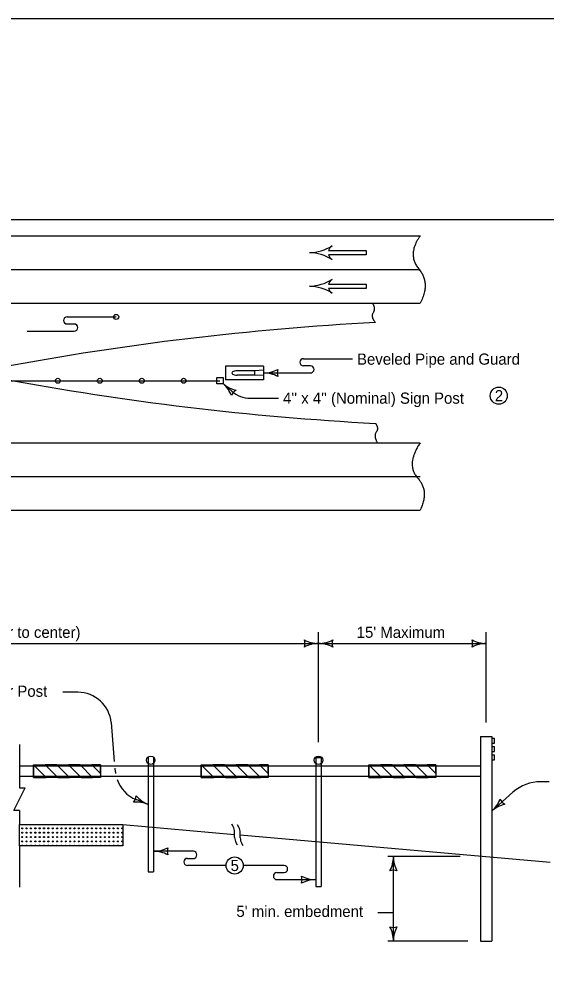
# Model space of a CAD drawing. Extents: x 228 to 3572, y -1307 to 1277.
# Drawn here: x 1702 to 2457, y -75 to 1277 of the extents above; entities that cross this region are included whole.
import ezdxf

# ---------------------------------------------------------------- set-up
doc = ezdxf.new("R2010")
doc.units = 0
for name, color, linetype in [('dsnShtPlotShapeBatchPrint', 7, 'Continuous'), ('dsnStdBorder', 7, 'Continuous'), ('dsnStdDimension', 7, 'Continuous'), ('Level 2', 7, 'Continuous'), ('Level 3', 7, 'Continuous')]:
    doc.layers.add(name, color=color, linetype=linetype)

msp = doc.modelspace()

# ---------------------------------------------------------------- linework, layer by layer
at = {"layer": 'dsnShtPlotShapeBatchPrint'}
msp.add_lwpolyline([(228, -1307), (3572, -1307), (3572, 1277), (228, 1277)], close=True, dxfattribs=at)
at = {"layer": 'dsnStdBorder'}
msp.add_lwpolyline([(332.5, 990), (3467.5, 990), (3467.5, -1020), (332.5, -1020)], close=True, dxfattribs=at)
at = {"layer": 'dsnStdDimension'}
for p, q in [((1771.2, 850.8), (1841.4, 850.8)), ((1781.3, 840.7), (1771.2, 840.7)), ((1714.2, 830.5), (1781.3, 830.5)), ((2109.3, 791), (2179.5, 791)), ((2052.3, 770.7), (2119.4, 770.7)), ((2119.4, 780.9), (2109.3, 780.9)), ((1994.4, 755.5), (2006.8, 744.6)), ((2033.3, 734.6), (2073.6, 734.6)), ((2130.9, 242.8), (2130.9, 399.9)), ((690.9, 383.9), (2130.9, 383.9)), ((2130.9, 383.9), (2370.9, 383.9)), ((1786.5, 314), (1765, 314)), ((1838.8, 215.1), (1834.5, 270.7)), ((1840.3, 200.4), (1839.8, 205.4)), ((2461.1, 186.1), (2448.9, 186.1)), ((2409.1, 171), (2378.9, 144.2)), ((1886.9, 153.8), (1869.9, 160.7)), ((1951.8, 86.7), (1894.9, 86.7)), ((1943.3, 76.6), (1953.4, 76.6)), ((2333.5, 79), (2230.1, 79)), ((2238.1, -41.7), (2238.1, 79)), ((1998.6, 66.4), (1943.3, 66.4)), ((2081.6, 66.4), (2023.1, 66.4)), ((2071.4, 56.2), (2081.6, 56.2)), ((2126.9, 46.1), (2071.4, 46.1)), ((2344.8, -41.7), (2230.1, -41.7))]:
    msp.add_line(p, q, dxfattribs=at)
msp.add_circle((1841.4, 850.8), 3.56, dxfattribs=at)
for centre, radius, start, end in [((1771.2, 845.8), 5.08, 90, 270), ((1781.3, 835.6), 5.08, 270, 90), ((2109.3, 786), 5.08, 90, 270), ((2052.3, 813.9), 43.2, 270, 298.0725), ((2052.3, 727.5), 43.2, 61.9275, 90), ((2088.5, 770.7), 16.7, 162.2666, 197.7334), ((2119.4, 775.8), 5.08, 270, 90), ((2022.9, 787.9), 43.2, 228.5996, 256.6721), ((1965.8, 723.2), 43.2, 20.5271, 48.5996), ((2021.5, 731.6), 16.7, 120.8663, 156.333), ((2033.3, 774.6), 40, 228.6035, 270), ((2094.7, 383.9), 16.7, 342.2666, 17.7333), ((2130.9, 427.1), 43.2, 241.9275, 270), ((2130.9, 340.7), 43.2, 90, 118.0725), ((2130.9, 427.1), 43.2, 270, 298.0725), ((2130.9, 340.7), 43.2, 61.9275, 90), ((2167.1, 383.9), 16.7, 162.2666, 197.7334), ((1786.5, 266), 48, 5.5839, 90), ((1888, 205.1), 48, 199.1127, 247.8452), ((2448.9, 126.1), 60, 90, 131.5444), ((1853.4, 167.4), 16.7, 320.1153, 355.582), ((1903.2, 193.8), 43.2, 219.7761, 247.8486), ((1870.6, 113.8), 43.2, 67.8486, 95.9211), ((2350.2, 176.5), 43.2, 311.5401, 339.6126), ((2407.5, 111.9), 43.2, 103.4676, 131.5401), ((2406, 168.2), 16.7, 203.8068, 239.2735), ((1894.9, 129.9), 43.2, 270, 298.0725), ((1894.9, 43.5), 43.2, 61.9275, 90), ((1931.1, 86.7), 16.7, 162.2667, 197.7334), ((1951.8, 81.6), 5.08, 270, 90), ((1943.3, 71.5), 5.08, 90, 270), ((2194.9, 79), 43.2, 331.9275, 0), ((2281.3, 79), 43.2, 180, 208.0725), ((2071.4, 51.2), 5.08, 90, 270), ((2081.6, 61.3), 5.08, 270, 90), ((2238.1, 42.8), 16.7, 72.2666, 107.7334), ((2090.7, 46.1), 16.7, 342.2667, 17.7334), ((2126.9, 89.3), 43.2, 241.9275, 270), ((2126.9, 2.9), 43.2, 90, 118.0725), ((2238.1, -5.5), 16.7, 252.2666, 287.7333), ((2194.9, -41.7), 43.2, 0, 28.0725), ((2281.3, -41.7), 43.2, 151.9275, 180)]:
    msp.add_arc(centre, radius, start, end, dxfattribs=at)
at = {"layer": 'Level 2'}
for p, q in [((519.5, 966.7), (2276.3, 966.7)), ((2145.3, 945.8), (2199.1, 945.8)), ((2199.1, 939.7), (2145.3, 939.7)), ((2199.1, 945.8), (2199.1, 939.7)), ((519.5, 918.7), (2276.3, 918.7)), ((2145.3, 897.8), (2199.1, 897.8)), ((2199.1, 897.8), (2199.1, 891.7)), ((2199.1, 891.7), (2145.3, 891.7)), ((519.5, 870.7), (2276.3, 870.7)), ((1997.9, 780.3), (1997.9, 761.1)), ((2052.3, 780.3), (1997.9, 780.3)), ((2039.5, 773.9), (2014.7, 773.9)), ((2052.3, 774.6), (2039.5, 773.9)), ((2039.5, 773.9), (2039.5, 767.5)), ((2052.3, 780.3), (2052.3, 761.1)), ((805.9, 759.5), (1989.9, 759.5)), ((2052.3, 761.1), (1997.9, 761.1)), ((2039.5, 767.5), (2014.7, 767.5)), ((2052.3, 766.9), (2039.5, 767.5)), ((519.5, 670.7), (2276.3, 670.7)), ((519.5, 622.7), (2276.3, 622.7)), ((519.5, 574.7), (2276.3, 574.7)), ((2370.9, 270.8), (2370.9, 399.9)), ((2362.9, 250.8), (2378.9, 250.8)), ((2362.9, 250.8), (2362.9, 79.7)), ((2378.9, 250.8), (2378.9, 78.3)), ((1702.9, 239.6), (1702.9, 177.3)), ((1886.9, 220.8), (1886.9, 121.6)), ((1894.9, 220.8), (1894.9, 120.9)), ((2126.9, 220.8), (2134.9, 220.8)), ((2126.9, 220.8), (2126.9, 100.5)), ((2134.9, 220.8), (2134.9, 99.8)), ((1702.9, 208.8), (2362.9, 208.8)), ((1739.6, 210.5), (1757.7, 192.4)), ((1756.3, 210.5), (1774.4, 192.4)), ((1773, 210.5), (1791.1, 192.4)), ((1789.6, 210.5), (1807.7, 192.4)), ((1806.3, 210.5), (1818.9, 198)), ((1979.6, 210.5), (1997.7, 192.4)), ((1996.3, 210.5), (2014.4, 192.4)), ((2013, 210.5), (2031.1, 192.4)), ((2029.6, 210.5), (2047.7, 192.4)), ((2046.3, 210.5), (2058.9, 198)), ((2219.6, 210.5), (2237.7, 192.4)), ((2236.3, 210.5), (2254.4, 192.4)), ((2253, 210.5), (2271.1, 192.4)), ((2269.6, 210.5), (2287.7, 192.4)), ((2286.3, 210.5), (2298.9, 198)), ((1702.9, 194.3), (2362.9, 194.3)), ((1694.9, 144.9), (1710.9, 177.3)), ((1702.9, 177.3), (1710.9, 177.3)), ((1702.9, 144.9), (1694.9, 144.9)), ((1702.9, 144.9), (1702.9, 124.8)), ((1702.9, 94.5), (1702.9, 124.8)), ((1702.9, 124.8), (1850.9, 124.8)), ((1702.9, 124.8), (1850.9, 124.8)), ((1850.9, 124.8), (1850.9, 94.5)), ((1850.9, 124.8), (2010.9, 110.7)), ((2008.7, 122.1), (2006.9, 125.3)), ((2016.7, 121.3), (2014.9, 124.5)), ((1886.9, 121.6), (1886.9, 57.4)), ((1894.9, 120.9), (1894.9, 57.4)), ((2010.9, 106.6), (2010.9, 114.1)), ((2018.9, 105.9), (2018.9, 113.3)), ((2018.9, 110), (2462.6, 70.9)), ((2014.9, 95.4), (2013, 98.6)), ((2022.9, 94.7), (2021, 97.9)), ((2126.9, 100.5), (2126.9, 36.2)), ((2134.9, 99.8), (2134.9, 36.2)), ((1702.9, 94.5), (1702.9, 35.5)), ((1850.9, 94.5), (1702.9, 94.5)), ((2362.9, 79.7), (2362.9, -41.7)), ((2378.9, 78.3), (2378.9, -41.7)), ((1886.9, 57.4), (1894.9, 57.4)), ((2126.9, 36.2), (2126.9, 36.2)), ((2126.9, 36.2), (2134.9, 36.2)), ((2238.1, -1.4), (2216, -1.4)), ((2362.9, -41.7), (2378.9, -41.7))]:
    msp.add_line(p, q, dxfattribs=at)
for points in [[(1985.4, 764), (1994.4, 764), (1994.4, 755), (1985.4, 755)], [(1985.4, 764), (1994.4, 764), (1994.4, 755), (1985.4, 755)], [(2382.9, 248), (2378.9, 248), (2378.9, 241.5), (2382.9, 241.5)], [(2382.9, 236), (2378.9, 236), (2378.9, 229.5), (2382.9, 229.5)], [(2382.9, 224), (2378.9, 224), (2378.9, 217.5), (2382.9, 217.5)], [(1722.9, 210.5), (1818.9, 210.5), (1818.9, 192.4), (1722.9, 192.4)], [(1722.9, 210.5), (1722.9, 192.4), (1741, 192.4)], [(1757.7, 192.4), (1774.4, 192.4), (1756.3, 210.5), (1739.6, 210.5)], [(1791.1, 192.4), (1807.7, 192.4), (1789.6, 210.5), (1773, 210.5)], [(1818.9, 198), (1818.9, 210.5), (1806.3, 210.5)], [(1962.9, 210.5), (2058.9, 210.5), (2058.9, 192.4), (1962.9, 192.4)], [(1962.9, 210.5), (1962.9, 192.4), (1981, 192.4)], [(1997.7, 192.4), (2014.4, 192.4), (1996.3, 210.5), (1979.6, 210.5)], [(2031.1, 192.4), (2047.7, 192.4), (2029.6, 210.5), (2013, 210.5)], [(2058.9, 198), (2058.9, 210.5), (2046.3, 210.5)], [(2202.9, 210.5), (2298.9, 210.5), (2298.9, 192.4), (2202.9, 192.4)], [(2202.9, 210.5), (2202.9, 192.4), (2221, 192.4)], [(2237.7, 192.4), (2254.4, 192.4), (2236.3, 210.5), (2219.6, 210.5)], [(2271.1, 192.4), (2287.7, 192.4), (2269.6, 210.5), (2253, 210.5)], [(2298.9, 198), (2298.9, 210.5), (2286.3, 210.5)]]:
    msp.add_lwpolyline(points, close=True, dxfattribs=at)
for centre, radius in [((1757.9, 759.5), 3.56), ((1817.9, 759.5), 3.56), ((1877.9, 759.5), 3.56), ((1937.9, 759.5), 3.56), ((2388.8, 738.2), 12.2), ((1890.9, 216.8), 6), ((2130.9, 216.8), 6), ((1707, 119.5), 0.711), ((1707, 113.3), 0.711), ((1713.2, 119.5), 0.711), ((1713.2, 113.3), 0.711), ((1719.4, 119.5), 0.711), ((1719.4, 113.3), 0.711), ((1725.7, 119.5), 0.711), ((1725.7, 113.3), 0.711), ((1731.9, 119.5), 0.711), ((1731.9, 113.3), 0.711), ((1738.1, 119.5), 0.711), ((1738.1, 113.3), 0.711), ((1744.3, 119.5), 0.711), ((1744.3, 113.3), 0.711), ((1750.6, 119.5), 0.711), ((1750.6, 113.3), 0.711), ((1756.8, 119.5), 0.711), ((1756.8, 113.3), 0.711), ((1763, 119.5), 0.711), ((1763, 113.3), 0.711), ((1769.2, 119.5), 0.711), ((1769.2, 113.3), 0.711), ((1775.4, 119.5), 0.711), ((1775.4, 113.3), 0.711), ((1781.7, 119.5), 0.711), ((1781.7, 113.3), 0.711), ((1787.9, 119.5), 0.711), ((1787.9, 113.3), 0.711), ((1794.1, 119.5), 0.711), ((1794.1, 113.3), 0.711), ((1800.3, 119.5), 0.711), ((1800.3, 113.3), 0.711), ((1806.6, 119.5), 0.711), ((1806.6, 113.3), 0.711), ((1812.8, 119.5), 0.711), ((1812.8, 113.3), 0.711), ((1819, 119.5), 0.711), ((1819, 113.3), 0.711), ((1825.2, 119.5), 0.711), ((1825.2, 113.3), 0.711), ((1831.4, 119.5), 0.711), ((1831.4, 113.3), 0.711), ((1837.7, 119.5), 0.711), ((1837.7, 113.3), 0.711), ((1843.9, 119.5), 0.711), ((1843.9, 113.3), 0.711), ((1850.1, 119.5), 0.711), ((1850.1, 113.3), 0.711), ((1707, 107), 0.711), ((1707, 100.8), 0.711), ((1713.2, 107), 0.711), ((1713.2, 100.8), 0.711), ((1719.4, 107), 0.711), ((1719.4, 100.8), 0.711), ((1725.7, 107), 0.711), ((1725.7, 100.8), 0.711), ((1731.9, 107), 0.711), ((1731.9, 100.8), 0.711), ((1738.1, 107), 0.711), ((1738.1, 100.8), 0.711), ((1744.3, 107), 0.711), ((1744.3, 100.8), 0.711), ((1750.6, 107), 0.711), ((1750.6, 100.8), 0.711), ((1756.8, 107), 0.711), ((1756.8, 100.8), 0.711), ((1763, 107), 0.711), ((1763, 100.8), 0.711), ((1769.2, 107), 0.711), ((1769.2, 100.8), 0.711), ((1775.4, 107), 0.711), ((1775.4, 100.8), 0.711), ((1781.7, 107), 0.711), ((1781.7, 100.8), 0.711), ((1787.9, 107), 0.711), ((1787.9, 100.8), 0.711), ((1794.1, 107), 0.711), ((1794.1, 100.8), 0.711), ((1800.3, 107), 0.711), ((1800.3, 100.8), 0.711), ((1806.6, 107), 0.711), ((1806.6, 100.8), 0.711), ((1812.8, 107), 0.711), ((1812.8, 100.8), 0.711), ((1819, 107), 0.711), ((1819, 100.8), 0.711), ((1825.2, 107), 0.711), ((1825.2, 100.8), 0.711), ((1831.4, 107), 0.711), ((1831.4, 100.8), 0.711), ((1837.7, 107), 0.711), ((1837.7, 100.8), 0.711), ((1843.9, 107), 0.711), ((1843.9, 100.8), 0.711), ((1850.1, 107), 0.711), ((1850.1, 100.8), 0.711), ((2010.9, 66.4), 12.2)]:
    msp.add_circle(centre, radius, dxfattribs=at)
for centre, radius, start, end in [((2115.9, 1008.2), 65.5, 271.6842, 301.7143), ((2156.4, 942.7), 11.5, 121.7147, 164.5877), ((2115.9, 877.2), 65.5, 58.2857, 88.3158), ((2156.4, 942.7), 11.5, 195.4195, 238.2853), ((2115.9, 960.2), 65.5, 271.6842, 301.7143), ((2115.9, 829.2), 65.5, 58.2857, 88.3158), ((2156.4, 894.7), 11.5, 121.7147, 164.5877), ((2156.4, 894.7), 11.5, 195.4195, 238.2853), ((2428.3, -3224.7), 4073.2, 93.04, 100.6164), ((2428.3, 4766.1), 4073.2, 259.3836, 266.96), ((2334.7, 383.9), 16.7, 342.2666, 17.7333), ((2370.9, 427.1), 43.2, 241.9275, 270), ((2370.9, 340.7), 43.2, 90, 118.0725), ((1888, 205.1), 48, 185.6396, 188.8502), ((1994.9, 114.1), 16, 0, 29.9788), ((2002.9, 113.3), 16, 0, 29.9673), ((1707, 94.6), 0.711, 351.6893, 188.3107), ((1713.2, 94.6), 0.711, 351.6893, 188.3107), ((1719.4, 94.6), 0.711, 351.6893, 188.3107), ((1725.7, 94.6), 0.711, 351.6893, 188.3107), ((1731.9, 94.6), 0.711, 351.6893, 188.3107), ((1738.1, 94.6), 0.711, 351.6893, 188.3107), ((1744.3, 94.6), 0.711, 351.6893, 188.3107), ((1750.6, 94.6), 0.711, 351.6893, 188.3107), ((1756.8, 94.6), 0.711, 351.6893, 188.3107), ((1763, 94.6), 0.711, 351.6893, 188.3107), ((1769.2, 94.6), 0.711, 351.6893, 188.3107), ((1775.4, 94.6), 0.711, 351.6893, 188.3107), ((1781.7, 94.6), 0.711, 351.6893, 188.3107), ((1787.9, 94.6), 0.711, 351.6893, 188.3107), ((1794.1, 94.6), 0.711, 351.6893, 188.3107), ((1800.3, 94.6), 0.711, 351.6893, 188.3107), ((1806.6, 94.6), 0.711, 351.6893, 188.3107), ((1812.8, 94.6), 0.711, 351.6893, 188.3107), ((1819, 94.6), 0.711, 351.6893, 188.3107), ((1825.2, 94.6), 0.711, 351.6893, 188.3107), ((1831.4, 94.6), 0.711, 351.6893, 188.3107), ((1837.7, 94.6), 0.711, 351.6893, 188.3107), ((1843.9, 94.6), 0.711, 351.6893, 188.3107), ((1850.1, 94.6), 0.711, 351.6893, 188.3107), ((2026.9, 106.6), 16, 180, 209.9996), ((2034.9, 105.9), 16, 180, 210.0017)]:
    msp.add_arc(centre, radius, start, end, dxfattribs=at)
msp.add_ellipse((2014.7, 770.7), major_axis=(7.77, 0), ratio=0.411692, start_param=1.570796, end_param=4.712389, dxfattribs=at)
for points in [[(2276.3, 966.7), (2257.3, 940), (2291.6, 898.7), (2276.3, 870.7)], [(2212.3, 842.7), (2205.8, 850.9), (2213.2, 863.6), (2208, 870.6)], [(2212.3, 698.7), (2217.5, 691.8), (2209.4, 680.4), (2215.3, 670.7)], [(2276.3, 670.7), (2255.5, 639.4), (2289.9, 601.6), (2276.3, 574.7)]]:
    msp.add_open_spline(points, degree=2, dxfattribs=at)

# ---------------------------------------------------------------- texts
at = {"layer": 'dsnStdDimension'}
for s, p in [('Beveled Pipe and Guard', (2186, 782.5)), ("4'' x 4'' (Nominal) Sign Post", (2080.1, 726.7)), ('Variable (Delineator Posts equally spaced at approximately 15 feet center to center)', (997, 391.9)), ("15' Maximum", (2185.5, 391.9)), ('Type 2 Steel Delineator Post', (1470.4, 307.6)), ("5' min. embedment", (2013.4, -7.2))]:
    msp.add_text(s, height=16, dxfattribs=at).set_placement(p)
at = {"layer": 'Level 3'}
for s, p in [('2', (2383.2, 730.2)), ('5', (2005.1, 58.4))]:
    msp.add_text(s, height=16, dxfattribs=at).set_placement(p)

doc.saveas('drawing.dxf')
